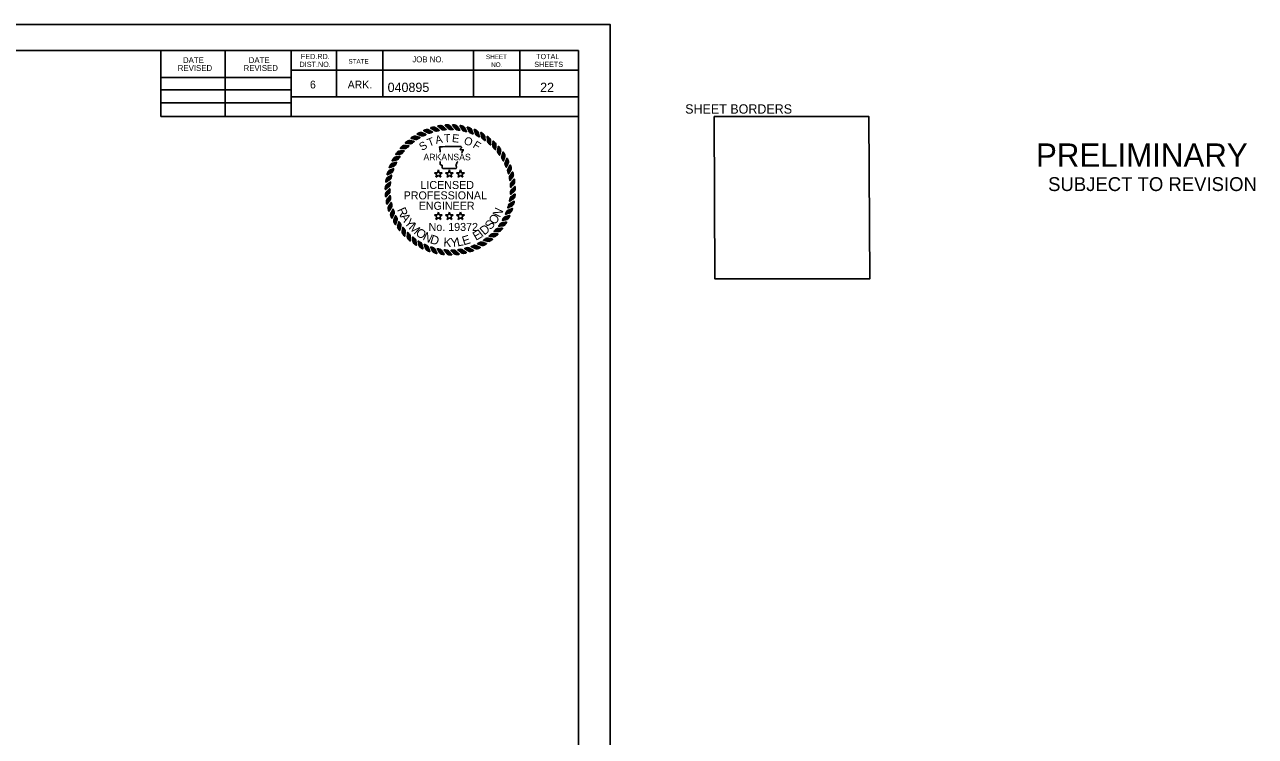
# Model space of a CAD drawing. Extents: x 1644315 to 1648839, y 578550 to 581749.
# Drawn here: x 1646874 to 1648719, y 579616 to 580683 of the extents above; entities that cross this region are included whole.
import ezdxf

# ---------------------------------------------------------------- set-up
doc = ezdxf.new("R2010")
doc.units = 0
for name, color, linetype in [('20', 7, 'Continuous'), ('Default', 7, 'Continuous'), ('R_Border', 7, 'Continuous'), ('R_Border PE', 7, 'Continuous'), ('R_No Plot', 7, 'Continuous')]:
    doc.layers.add(name, color=color, linetype=linetype)

# ---------------------------------------------------------------- blocks, each defined once
blk = doc.blocks.new('ROP')
at = {"layer": 'Default'}
for points in [[(0.0053, 0.0002), (0.0001, 0.0006), (-0.0001, -0.0001), (0.0048, -0.0005)], [(0.0058, 0.0009), (0.0005, 0.0013), (0.0003, 0.0006), (0.0053, 0.0002)], [(0.0007, 0.0014), (0.006, 0.001), (0.0062, 0.0017), (0.0012, 0.0021)], [(0.0007, 0.0013), (0.0058, 0.0009), (0.0059, 0.001), (0.0008, 0.0014)], [(0.0011, 0.0021), (0.0063, 0.0016), (0.0064, 0.0027), (0.0023, 0.0031)], [(0.0023, 0.003), (0.0063, 0.0027), (0.0064, 0.0035), (0.0032, 0.0038)], [(0.0032, 0.0038), (0.0064, 0.0035), (0.0064, 0.0042), (0.0039, 0.0044)], [(0.004, 0.0044), (0.0064, 0.0042), (0.0065, 0.0047), (0.0046, 0.0048)], [(0.0045, 0.0048), (0.0066, 0.0047), (0.0066, 0.0051), (0.005, 0.0052)], [(0.0049, 0.0052), (0.0066, 0.0051), (0.0066, 0.0054), (0.0053, 0.0055)], [(0.0052, 0.0055), (0.0066, 0.0054), (0.0066, 0.0057), (0.0056, 0.0058)], [(0.0056, 0.0058), (0.0067, 0.0057), (0.0066, 0.006), (0.0058, 0.006)], [(0.0058, 0.006), (0.0066, 0.006), (0.0065, 0.0062), (0.006, 0.0062)], [(0.0059, 0.0062), (0.0066, 0.0061), (0.0066, 0.0063), (0.006, 0.0064)], [(0.0061, 0.0064), (0.0065, 0.0063), (0.0065, 0.0064), (0.0061, 0.0064)], [(0.0026, -0.0024), (-0.0003, -0.0021), (-0.0004, -0.0028), (0.002, -0.003)], [(-0.0003, -0.0036), (0.0013, -0.0037), (0.0019, -0.003), (-0.0004, -0.0028)], [(-0.0004, -0.004), (0.0007, -0.0041), (0.0011, -0.0037), (-0.0004, -0.0036)], [(-0.0004, -0.0044), (0.0004, -0.0044), (0.0007, -0.0041), (-0.0004, -0.004)], [(-0.0003, -0.0014), (0.0033, -0.0017), (0.0038, -0.0013), (-0.0002, -0.0009)], [(0.0034, -0.0017), (-0.0003, -0.0014), (-0.0003, -0.0021), (0.0026, -0.0024)], [(-0.0003, -0.0028), (0.0019, -0.003), (0.0019, -0.003), (-0.0003, -0.0028)], [(-0.0002, -0.0005), (0.0043, -0.0009), (0.0046, -0.0005), (-0.0002, -0.0001)], [(-0.0002, -0.0046), (0.0003, -0.0046), (0.0005, -0.0044), (-0.0002, -0.0044)], [(-0.0001, -0.0047), (0.0003, -0.0047), (0.0003, -0.0046), (-0.0002, -0.0046)], [(-0.0001, -0.0009), (0.0038, -0.0013), (0.0042, -0.0009), (-0.0001, -0.0005)]]:
    blk.add_lwpolyline(points, close=True, dxfattribs=at)
blk.add_open_spline([(0.0001, -0.0048), (-0.0002, -0.0046), (-0.0004, -0.0043), (-0.0004, -0.0041), (-0.0004, -0.0025), (-0.0001, -0.0003), (0, -0.0002), (0.0001, 0.0004), (0.0003, 0.0008), (0.0004, 0.0009), (0.0005, 0.0012), (0.0007, 0.0014), (0.0009, 0.0018), (0.0012, 0.0021), (0.0014, 0.0023), (0.0016, 0.0025), (0.0019, 0.0028), (0.0024, 0.0032), (0.0026, 0.0034), (0.0028, 0.0035), (0.0033, 0.0039), (0.0042, 0.0046), (0.0051, 0.0054), (0.0053, 0.0055), (0.0056, 0.0058), (0.0062, 0.0065), (0.0064, 0.0065), (0.0066, 0.0063), (0.0066, 0.0054), (0.0063, 0.0019), (0.0061, 0.0012), (0.0056, 0.0003), (0.0054, 0.0001), (0.0052, -0.0001), (0.0049, -0.0005), (0.0046, -0.0007), (0.0044, -0.0008), (0.0038, -0.0013), (0.0036, -0.0015), (0.0034, -0.0017), (0.0028, -0.0023), (0.0027, -0.0024), (0.0023, -0.0026), (0.0022, -0.0028), (0.0019, -0.0031), (0.0016, -0.0034), (0.0012, -0.0037), (0.0008, -0.004), (0.0007, -0.0042), (0.0004, -0.0046), (0.0001, -0.0048)], degree=2, dxfattribs=at)

msp = doc.modelspace()

# ---------------------------------------------------------------- linework, layer by layer
at = {"layer": '20'}
msp.add_line((1644418.6, 580683.1), (1647751.9, 580683.1), dxfattribs=at)
for points in [[(1644418.5, 580683.1), (1647751.9, 580683.1), (1647751.9, 578549.7), (1644418.5, 578549.7)], [(1647907.6, 580545.4), (1648139.7, 580545.4), (1648140.9, 580302), (1647908.8, 580302)]]:
    msp.add_lwpolyline(points, close=True, dxfattribs=at)
at = {"layer": 'R_Border'}
for p, q in [((1647492.9, 580461.1), (1647488.5, 580461.1)), ((1647488.5, 580461.1), (1647492.1, 580458.5)), ((1647494.3, 580465.3), (1647492.9, 580461.1)), ((1647495.6, 580461.1), (1647494.3, 580465.3)), ((1647500.1, 580461.1), (1647495.6, 580461.1)), ((1647496.4, 580458.5), (1647500.1, 580461.1)), ((1647509.5, 580461.1), (1647505, 580461.1)), ((1647505, 580461.1), (1647508.6, 580458.5)), ((1647510.8, 580465.3), (1647509.5, 580461.1)), ((1647512.2, 580461.1), (1647510.8, 580465.3)), ((1647516.6, 580461.1), (1647512.2, 580461.1)), ((1647513, 580458.5), (1647516.6, 580461.1)), ((1647525.2, 580458.5), (1647521.6, 580461.1)), ((1647521.6, 580461.1), (1647526, 580461.1)), ((1647526, 580461.1), (1647527.4, 580465.3)), ((1647527.4, 580465.3), (1647528.7, 580461.1)), ((1647528.7, 580461.1), (1647533.2, 580461.1)), ((1647533.2, 580461.1), (1647529.6, 580458.5)), ((1647492.1, 580458.5), (1647490.7, 580454.3)), ((1647490.7, 580454.3), (1647494.3, 580456.9)), ((1647494.3, 580456.9), (1647497.8, 580454.3)), ((1647497.8, 580454.3), (1647496.4, 580458.5)), ((1647508.6, 580458.5), (1647507.3, 580454.3)), ((1647507.3, 580454.3), (1647510.8, 580456.9)), ((1647510.8, 580456.9), (1647514.3, 580454.3)), ((1647514.3, 580454.3), (1647513, 580458.5)), ((1647523.8, 580454.3), (1647525.2, 580458.5)), ((1647527.4, 580456.9), (1647523.8, 580454.3)), ((1647530.9, 580454.3), (1647527.4, 580456.9)), ((1647529.6, 580458.5), (1647530.9, 580454.3)), ((1647492.9, 580397.8), (1647488.5, 580397.8)), ((1647488.5, 580397.8), (1647492.1, 580395.2)), ((1647492.1, 580395.2), (1647490.7, 580391)), ((1647490.7, 580391), (1647494.3, 580393.6)), ((1647494.3, 580402), (1647492.9, 580397.8)), ((1647495.6, 580397.8), (1647494.3, 580402)), ((1647494.3, 580393.6), (1647497.8, 580391.1)), ((1647500.1, 580397.8), (1647495.6, 580397.8)), ((1647496.4, 580395.2), (1647500.1, 580397.8)), ((1647497.8, 580391.1), (1647496.4, 580395.2)), ((1647509.5, 580397.8), (1647505, 580397.8)), ((1647505, 580397.8), (1647508.6, 580395.2)), ((1647508.6, 580395.2), (1647507.3, 580391)), ((1647507.3, 580391), (1647510.8, 580393.6)), ((1647510.8, 580402), (1647509.5, 580397.8)), ((1647512.2, 580397.8), (1647510.8, 580402)), ((1647510.8, 580393.6), (1647514.3, 580391.1)), ((1647516.6, 580397.8), (1647512.2, 580397.8)), ((1647513, 580395.2), (1647516.6, 580397.8)), ((1647514.3, 580391.1), (1647513, 580395.2)), ((1647525.2, 580395.2), (1647521.6, 580397.8)), ((1647521.6, 580397.8), (1647526, 580397.8)), ((1647523.8, 580391.1), (1647525.2, 580395.2)), ((1647527.4, 580393.6), (1647523.8, 580391.1)), ((1647526, 580397.8), (1647527.4, 580402)), ((1647527.4, 580402), (1647528.7, 580397.8)), ((1647530.9, 580391), (1647527.4, 580393.6)), ((1647528.7, 580397.8), (1647533.2, 580397.8)), ((1647533.2, 580397.8), (1647529.6, 580395.2)), ((1647529.6, 580395.2), (1647530.9, 580391))]:
    msp.add_line(p, q, dxfattribs=at)
for points in [[(1647528.2, 580500.3), (1647496.8, 580500.3), (1647496, 580499.9), (1647496, 580499.5), (1647496.5, 580497.2), (1647496.8, 580495.1), (1647496.9, 580492.6), (1647497, 580492)], [(1647529, 580490.7), (1647529.1, 580490.8), (1647529.5, 580491.1), (1647530, 580491.7), (1647530.3, 580492.4), (1647529.6, 580493), (1647530.5, 580493.4), (1647530.7, 580493.2), (1647531.3, 580493.7), (1647531.3, 580494.4), (1647531.5, 580495.1), (1647531.8, 580495.5), (1647531.1, 580495.6), (1647529.3, 580495.6), (1647527.7, 580495.6), (1647526.9, 580495.7), (1647526.8, 580496.2), (1647527.6, 580497), (1647528.7, 580498), (1647529, 580498.8), (1647528.7, 580499.6), (1647528.4, 580500.1), (1647528, 580500.4)], [(1647497.2, 580478), (1647497.2, 580477.8), (1647497.2, 580476.6), (1647497.1, 580475.6), (1647496.9, 580474.1), (1647497, 580473.4), (1647497.4, 580472.9), (1647499, 580472.6), (1647500.1, 580472.7), (1647500.2, 580472.1), (1647500.2, 580469.2), (1647500.2, 580467.6), (1647500.8, 580467.3), (1647514.8, 580467.3), (1647520.9, 580467.3), (1647521.2, 580468), (1647521.1, 580468.5), (1647521.6, 580468.9), (1647521.9, 580469.6), (1647521.5, 580470.3), (1647520.8, 580471.1), (1647520.7, 580471.6), (1647521, 580472.2), (1647520.6, 580472.7), (1647520.7, 580473.3), (1647521.3, 580473.7), (1647521.7, 580474.1), (1647521.3, 580474.5), (1647522, 580475.1), (1647522.1, 580475.6), (1647522, 580476.5), (1647522.9, 580477.1), (1647523.3, 580477.3), (1647523.2, 580477.8), (1647523.2, 580478)]]:
    msp.add_open_spline(points, degree=3, dxfattribs=at)
at = {"layer": 'R_Border PE'}
for p, q in [((1644542.6, 580644.2), (1647704.4, 580644.2)), ((1647078, 580545.4), (1647078, 580644.2)), ((1647174.8, 580545.4), (1647174.8, 580644.2)), ((1647273.4, 580644.2), (1647273.4, 580545.4)), ((1647341.8, 580644.2), (1647341.8, 580574.8)), ((1647411.2, 580644.2), (1647411.2, 580574.8)), ((1647547, 580644.2), (1647547, 580574.8)), ((1647616.4, 580644.2), (1647616.4, 580574.8)), ((1647704.4, 578589.6), (1647704.4, 580644.2)), ((1647704.4, 580614.8), (1647273.4, 580614.8)), ((1647704.4, 580615), (1647704.4, 580615)), ((1647078, 580604), (1647273.4, 580604)), ((1647078, 580585.4), (1647273.4, 580585.4)), ((1647704.4, 580574.8), (1647273.4, 580574.8)), ((1647303, 580574.8), (1647704.4, 580574.8)), ((1647078, 580566), (1647273.4, 580566)), ((1647704.4, 580545.4), (1647078, 580545.4))]:
    msp.add_line(p, q, dxfattribs=at)

# ---------------------------------------------------------------- block references
at = {"layer": 'R_Border'}
for p, xscale, yscale, rotation in [((1647457.4, 580515.6), 1026.9161985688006, 1026.9161985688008, -55.63636363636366), ((1647466.8, 580521.3), 1026.9161985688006, 1026.9161985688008, -62.18181818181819), ((1647476.9, 580525.9), 1026.9161985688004, 1026.9161985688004, -68.72727272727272), ((1647487.5, 580529.4), 1026.9161985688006, 1026.9161985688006, -75.27272727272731), ((1647498.3, 580531.6), 1026.9161985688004, 1026.9161985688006, -81.81818181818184), ((1647509.4, 580532.5), 1026.9161985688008, 1026.916198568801, -88.36363636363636), ((1647520.4, 580532.2), 1026.9161985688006, 1026.9161985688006, -94.90909090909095), ((1647531.4, 580530.6), 1026.9161985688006, 1026.9161985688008, -101.45454545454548), ((1647542.1, 580527.8), 1026.9161985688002, 1026.9161985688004, -108.00000000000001), ((1647552.4, 580523.8), 1026.9161985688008, 1026.9161985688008, -114.54545454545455), ((1647562.2, 580518.6), 1026.9161985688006, 1026.9161985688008, -121.09090909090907), ((1647571.4, 580512.3), 1026.9161985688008, 1026.9161985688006, -127.63636363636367), ((1647433.6, 580492.5), 1026.9161985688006, 1026.9161985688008, -35.99999999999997), ((1647440.6, 580501.1), 1026.9161985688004, 1026.9161985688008, -42.54545454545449), ((1647448.6, 580508.8), 1026.9161985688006, 1026.916198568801, -49.09090909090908), ((1647579.8, 580505.1), 1026.9161985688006, 1026.9161985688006, -134.18181818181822), ((1647587.2, 580496.9), 1026.9161985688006, 1026.916198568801, -140.72727272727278), ((1647422.8, 580473.3), 1026.9161985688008, 1026.9161985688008, -22.909090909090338), ((1647427.6, 580483.2), 1026.9161985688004, 1026.9161985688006, -29.454545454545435), ((1647593.8, 580488), 1026.9161985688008, 1026.9161985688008, -147.27272727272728), ((1647599.2, 580478.3), 1026.9161985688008, 1026.9161985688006, -153.81818181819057), ((1647419, 580462.8), 1026.9161985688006, 1026.9161985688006, -16.36363636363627), ((1647603.5, 580468.1), 1026.9161985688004, 1026.9161985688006, -160.3636363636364), ((1647606.6, 580457.5), 1026.9161985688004, 1026.9161985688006, -166.90909090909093), ((1647415.3, 580441), 1026.916198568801, 1026.9161985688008, -3.2727272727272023), ((1647416.5, 580452.1), 1026.9161985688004, 1026.9161985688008, -9.818181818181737), ((1647608.5, 580446.6), 1026.9161985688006, 1026.9161985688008, -173.45454545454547), ((1647415.3, 580430), 1026.916198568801, 1026.9161985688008, 3.272727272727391), ((1647416.5, 580419), 1026.9161985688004, 1026.9161985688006, 9.818181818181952), ((1647608.5, 580424.4), 1026.9161985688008, 1026.9161985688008, 173.4545454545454), ((1647609.2, 580435.5), 1026.9161985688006, 1026.9161985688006, 180), ((1647419, 580408.2), 1026.9161985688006, 1026.9161985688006, 16.363636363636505), ((1647422.8, 580397.7), 1026.9161985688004, 1026.9161985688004, 22.90909090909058), ((1647603.5, 580402.9), 1026.9161985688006, 1026.9161985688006, 160.36363636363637), ((1647606.6, 580413.5), 1026.9161985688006, 1026.9161985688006, 166.90909090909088), ((1647427.6, 580387.8), 1026.9161985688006, 1026.9161985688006, 29.45454545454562), ((1647433.6, 580378.5), 1026.9161985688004, 1026.9161985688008, 36.000000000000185), ((1647593.8, 580383), 1026.9161985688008, 1026.9161985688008, 147.27272727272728), ((1647599.2, 580392.7), 1026.9161985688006, 1026.9161985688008, 153.81818181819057), ((1647440.6, 580369.9), 1026.9161985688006, 1026.9161985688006, 42.54545454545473), ((1647448.6, 580362.2), 1026.9161985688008, 1026.9161985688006, 49.09090909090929), ((1647579.8, 580365.9), 1026.9161985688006, 1026.9161985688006, 134.18181818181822), ((1647587.2, 580374.1), 1026.9161985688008, 1026.9161985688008, 140.72727272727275), ((1647457.4, 580355.4), 1026.9161985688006, 1026.9161985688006, 55.63636363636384), ((1647466.8, 580349.7), 1026.9161985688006, 1026.916198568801, 62.18181818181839), ((1647476.9, 580345.1), 1026.9161985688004, 1026.9161985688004, 68.72727272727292), ((1647487.5, 580341.7), 1026.9161985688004, 1026.9161985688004, 75.27272727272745), ((1647542.1, 580343.2), 1026.9161985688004, 1026.9161985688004, 108.00000000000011), ((1647552.4, 580347.2), 1026.9161985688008, 1026.9161985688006, 114.54545454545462), ((1647562.2, 580352.4), 1026.9161985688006, 1026.9161985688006, 121.09090909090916), ((1647571.4, 580358.7), 1026.9161985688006, 1026.9161985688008, 127.6363636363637), ((1647498.3, 580339.5), 1026.9161985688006, 1026.9161985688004, 81.81818181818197), ((1647509.4, 580338.5), 1026.9161985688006, 1026.916198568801, 88.3636363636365), ((1647520.4, 580338.8), 1026.9161985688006, 1026.916198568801, 94.90909090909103), ((1647531.4, 580340.4), 1026.9161985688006, 1026.9161985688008, 101.45454545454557)]:
    msp.add_blockref('ROP', p, dxfattribs=dict(at, xscale=xscale, yscale=yscale, rotation=rotation))

# ---------------------------------------------------------------- texts
for s, height, rotation, p in [('A', 12, 12.3722, (1647490.9, 580504.1)), ('T', 12, 2.5545, (1647502.9, 580506.7)), ('E', 12, 353.5585, (1647514.2, 580507.3)), ('S', 12, 31.1859, (1647469.8, 580493.5)), ('T', 12, 21.3682, (1647480.4, 580499.9)), ('O', 12, 339.6466, (1647531.4, 580504.7)), ('F', 12, 328.1996, (1647544.8, 580499.6)), ('R', 13.2, 294.0485, (1647432.1, 580405.7)), ('N', 13.2, 64.1529, (1647586.6, 580393.1)), ('A', 13.2, 301.5532, (1647436.7, 580395.5)), ('Y', 13.2, 309.0579, (1647442.5, 580385.9)), ('M', 13.2, 315.9343, (1647448.9, 580378)), ('S', 13.2, 48.5153, (1647572.4, 580374.7)), ('O', 13.2, 55.3916, (1647579.3, 580382.3)), ('O', 13.2, 325.3122, (1647459.1, 580368.4)), ('N', 13.2, 334.0735, (1647469.9, 580361.1)), ('D', 13.2, 342.2065, (1647480.9, 580355.9)), ('E', 13.2, 17.2399, (1647532.2, 580352.2)), ('E', 13.2, 30.376, (1647550.6, 580359)), ('I', 13.2, 37.2524, (1647559.4, 580364.1)), ('D', 13.2, 40.3823, (1647563.2, 580366.8)), ('K', 13.2, 356.5992, (1647501.6, 580350.6)), ('Y', 13.2, 4.1038, (1647512.8, 580349.9)), ('L', 13.2, 10.9802, (1647523, 580350.6))]:
    msp.add_text(s, height=height, rotation=rotation, dxfattribs=at).set_placement(p)
for s, height, p in [('ARKANSAS', 9.72, (1647472, 580479.8)), ('LICENSED', 12, (1647467.4, 580436.8)), ('PROFESSIONAL', 12, (1647442.2, 580421.2)), ('ENGINEER', 12, (1647464.8, 580405.6)), ('No. 19372', 12, (1647479.6, 580373.9))]:
    msp.add_text(s, height=height, dxfattribs=at).set_placement(p)
at = {"layer": 'R_Border PE'}
for s, height, p in [('DATE', 8.79, (1647111.4, 580625.5)), ('DATE', 8.79, (1647210, 580625.5)), ('DIST.NO.', 7.82, (1647286.2, 580619.6)), ('FED.RD.', 7.82, (1647288.2, 580631.4)), ('STATE', 6.84, (1647359.4, 580624.6)), ('JOB NO.', 8.79, (1647455.2, 580626.6)), ('SHEET', 6.84, (1647565.6, 580631.4)), ('NO.', 6.84, (1647573.4, 580619.6)), ('SHEETS', 7.82, (1647638, 580619.6)), ('TOTAL', 7.82, (1647640.8, 580631.4)), ('REVISED', 8.79, (1647103.6, 580613.7)), ('REVISED', 8.79, (1647202.2, 580613.7)), ('6', 11.7, (1647301.8, 580587.4)), ('ARK.', 11.72, (1647358.4, 580587.4)), ('040895', 14, (1647418.2, 580582.1)), ('22', 14, (1647646.8, 580582.1)), ('SHEET BORDERS', 14, (1647864.3, 580549.7))]:
    msp.add_text(s, height=height, dxfattribs=at).set_placement(p)
at = {"layer": 'R_No Plot'}
for s, height, p in [('PRELIMINARY', 35, (1648390.2, 580470)), ('SUBJECT TO REVISION', 20.751, (1648408.3, 580433.7))]:
    msp.add_text(s, height=height, dxfattribs=at).set_placement(p)

doc.saveas('drawing.dxf')
